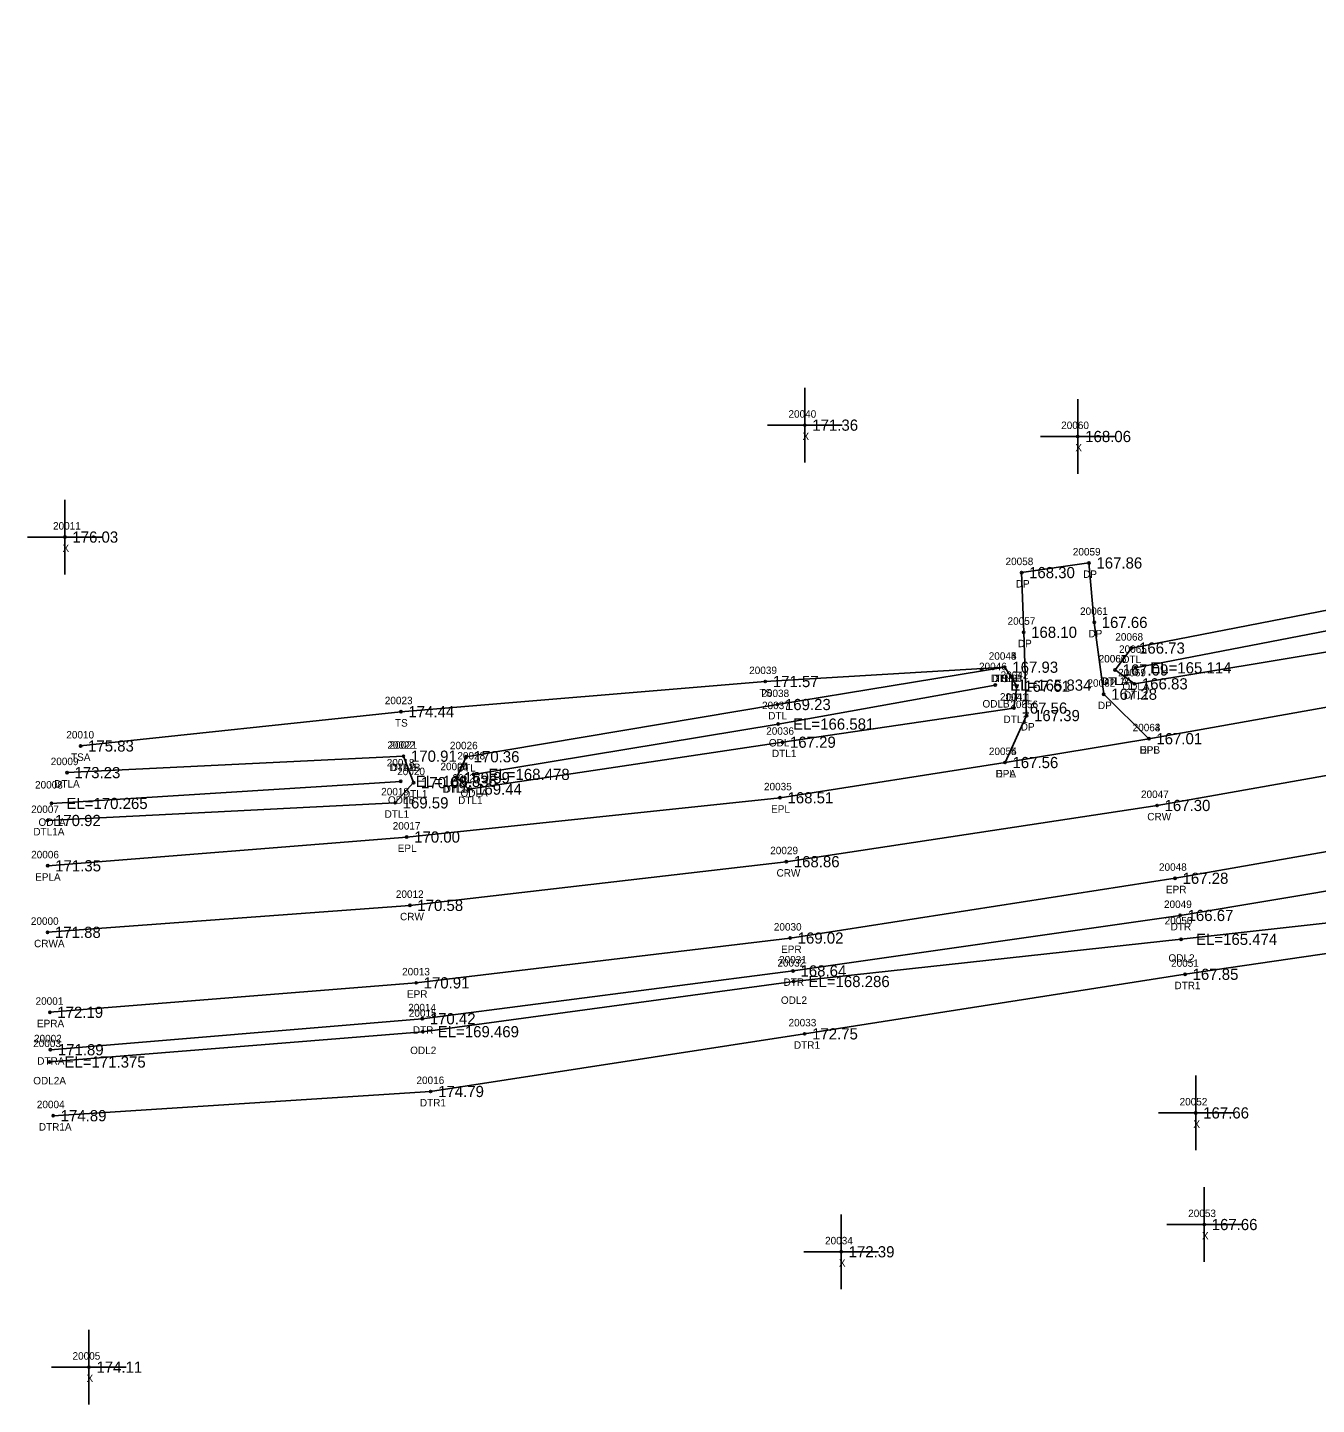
# Model space of a CAD drawing. Extents: x 2381545 to 2382928, y 1029933 to 1030589.
# Drawn here: x 2381544.5 to 2381717.1, y 1030195.9 to 1030380.3 of the extents above; entities that cross this region are included whole.
import ezdxf

# ---------------------------------------------------------------- set-up
doc = ezdxf.new("R2010")
doc.units = 0
for name, color, linetype in [('RD_DTM_BkLn1', 7, 'Continuous'), ('RD_DTM_BkLn2', 7, 'Continuous'), ('RD_DTM_BkLn_txCode', 7, 'Continuous'), ('RD_EX_Driveway', 7, 'Continuous'), ('RD_EX_Driveway_txCode', 7, 'Continuous'), ('RD_EX_H2O', 7, 'Continuous'), ('RD_EX_H2O_txCode', 7, 'Continuous'), ('RD_EX_Misc', 7, 'Continuous'), ('RD_EX_Misc_txCode', 7, 'Continuous'), ('RD_EX_Road', 7, 'Continuous'), ('RD_EX_Road_txCode', 7, 'Continuous'), ('RD_EX_TX_Driveway_ELEV', 7, 'Continuous'), ('RD_EX_TX_H2O_ELEV', 7, 'Continuous'), ('RD_EX_TX_Misc_ELEV', 7, 'Continuous'), ('RD_EX_TX_Road_ELEV', 7, 'Continuous'), ('RD_HC_Survey_ELEV', 7, 'Continuous'), ('RD_HC_Survey_txCode', 7, 'Continuous'), ('RD_SMD_Locator', 7, 'Continuous')]:
    doc.layers.add(name, color=color, linetype=linetype)

msp = doc.modelspace()

# ---------------------------------------------------------------- linework, layer by layer
at = {"layer": 'RD_DTM_BkLn1'}
msp.add_lwpolyline([(2381547.18, 1030259.1), (2381595.71, 1030262.71), (2381646.12, 1030268.56), (2381695.78, 1030276.09), (2381799.52, 1030294.49), (2381897.44, 1030312.39), (2382008.24, 1030333.66), (2382118.08, 1030354.86), (2382202.13, 1030371.04)], dxfattribs=at)
at = {"layer": 'RD_DTM_BkLn2'}
msp.add_lwpolyline([(2381551.61, 1030284.06), (2381594.51, 1030288.65), (2381643.31, 1030292.69), (2381675.39, 1030294.61)], dxfattribs=at)
at = {"layer": 'RD_EX_Driveway'}
msp.add_lwpolyline([(2381675.41, 1030281.84), (2381678.3, 1030288.13), (2381677.91, 1030299.29), (2381677.63, 1030307.28), (2381686.65, 1030308.57), (2381687.36, 1030300.61), (2381688.63, 1030290.99), (2381694.68, 1030285.03)], dxfattribs=at)
at = {"layer": 'RD_EX_H2O'}
for p, q in [((2381692.86, 1030294.53), (2381793.09, 1030313.94)), ((2381549.8, 1030280.49), (2381594.85, 1030282.69)), ((2381547.71, 1030276.36), (2381594.48, 1030279.32))]:
    msp.add_line(p, q, dxfattribs=at)
for points in [[(2381690.14, 1030294.24), (2381692.74, 1030292.38), (2381796.89, 1030309.66), (2381793.09, 1030313.94), (2381792.54, 1030316.64)], [(2381690.14, 1030294.24), (2381692.36, 1030297.17), (2381792.54, 1030316.64)], [(2381601.96, 1030279.81), (2381603.58, 1030278.28), (2381645.61, 1030284.56), (2381676.61, 1030289.13), (2381676.98, 1030292.06), (2381675.39, 1030294.61)], [(2381601.96, 1030279.81), (2381603.25, 1030282.62), (2381644.94, 1030289.61), (2381675.39, 1030294.61)], [(2381604.23, 1030280.25), (2381645.03, 1030286.99), (2381674.11, 1030292.21)], [(2381547.18, 1030274.08), (2381593.74, 1030276.44), (2381596.2, 1030279.15), (2381594.85, 1030282.69)], [(2381547.56, 1030243.37), (2381597.37, 1030247.52), (2381647.02, 1030253.93), (2381698.86, 1030261.36), (2381785.89, 1030275.89), (2381786.8, 1030272.08), (2381786.92, 1030266.26)], [(2381547.45, 1030241.73), (2381597.44, 1030245.79), (2381647.09, 1030252.51), (2381698.99, 1030258.16), (2381773.74, 1030266.5), (2381786.8, 1030272.08)], [(2381547.94, 1030234.54), (2381598.49, 1030237.78), (2381648.57, 1030245.5), (2381699.53, 1030253.48), (2381786.92, 1030266.26)]]:
    msp.add_lwpolyline(points, dxfattribs=at)
at = {"layer": 'RD_EX_Misc'}
for p, q in [((2381648.6, 1030322.03), (2381648.6, 1030332.03)), ((2381685.15, 1030320.51), (2381685.15, 1030330.51)), ((2381643.6, 1030327.03), (2381653.6, 1030327.03)), ((2381680.15, 1030325.51), (2381690.15, 1030325.51)), ((2381549.51, 1030307.04), (2381549.51, 1030317.04)), ((2381544.51, 1030312.04), (2381554.51, 1030312.04)), ((2381700.95, 1030229.91), (2381700.95, 1030239.91)), ((2381695.95, 1030234.91), (2381705.95, 1030234.91)), ((2381702.09, 1030214.96), (2381702.09, 1030224.96)), ((2381653.47, 1030211.31), (2381653.47, 1030221.31)), ((2381697.09, 1030219.96), (2381707.09, 1030219.96)), ((2381648.47, 1030216.31), (2381658.47, 1030216.31)), ((2381552.73, 1030195.86), (2381552.73, 1030205.86)), ((2381547.73, 1030200.86), (2381557.73, 1030200.86))]:
    msp.add_line(p, q, dxfattribs=at)
at = {"layer": 'RD_EX_Road'}
for points in [[(2381547.21, 1030268.01), (2381595.28, 1030271.86), (2381645.28, 1030277.12), (2381675.41, 1030281.84), (2381694.68, 1030285.03), (2381797.68, 1030303.35), (2381895.95, 1030322.08), (2382005.53, 1030342.57), (2382116.42, 1030363.72), (2382200, 1030380.28), (2382202.13, 1030371.04)], [(2381547.49, 1030248.39), (2381596.55, 1030252.33), (2381646.64, 1030258.33), (2381698.19, 1030266.34), (2381800.73, 1030284.35), (2381899.22, 1030302.47), (2382010.02, 1030323.79), (2382119.81, 1030345.41), (2382204.69, 1030361.31), (2382202.13, 1030371.04)]]:
    msp.add_lwpolyline(points, dxfattribs=at)
at = {"layer": 'RD_SMD_Locator'}
for centre in [(2381648.6, 1030327.03), (2381685.15, 1030325.51), (2381549.51, 1030312.04), (2381686.65, 1030308.57), (2381677.63, 1030307.28), (2381687.36, 1030300.61), (2381677.91, 1030299.29), (2381692.36, 1030297.17), (2381675.39, 1030294.61), (2381675.39, 1030294.61), (2381675.39, 1030294.61), (2381690.14, 1030294.24), (2381690.14, 1030294.24), (2381692.86, 1030294.53), (2381643.31, 1030292.69), (2381674.11, 1030292.21), (2381676.98, 1030292.06), (2381692.74, 1030292.38), (2381688.63, 1030290.99), (2381594.51, 1030288.65), (2381644.94, 1030289.61), (2381676.61, 1030289.13), (2381645.03, 1030286.99), (2381678.3, 1030288.13), (2381694.68, 1030285.03), (2381694.68, 1030285.03), (2381551.61, 1030284.06), (2381645.61, 1030284.56), (2381594.85, 1030282.69), (2381594.85, 1030282.69), (2381603.25, 1030282.62), (2381675.41, 1030281.84), (2381675.41, 1030281.84), (2381549.8, 1030280.49), (2381594.48, 1030279.32), (2381596.2, 1030279.15), (2381601.96, 1030279.81), (2381601.96, 1030279.81), (2381604.23, 1030280.25), (2381603.58, 1030278.28), (2381547.71, 1030276.36), (2381593.74, 1030276.44), (2381645.28, 1030277.12), (2381695.78, 1030276.09), (2381547.18, 1030274.08), (2381595.28, 1030271.86), (2381547.21, 1030268.01), (2381646.12, 1030268.56), (2381698.19, 1030266.34), (2381595.71, 1030262.71), (2381698.86, 1030261.36), (2381547.18, 1030259.1), (2381646.64, 1030258.33), (2381698.99, 1030258.16), (2381647.02, 1030253.93), (2381699.53, 1030253.48), (2381596.55, 1030252.33), (2381647.09, 1030252.51), (2381547.49, 1030248.39), (2381597.37, 1030247.52), (2381597.44, 1030245.79), (2381648.57, 1030245.5), (2381547.56, 1030243.37), (2381547.45, 1030241.73), (2381598.49, 1030237.78), (2381700.95, 1030234.91), (2381547.94, 1030234.54), (2381702.09, 1030219.96), (2381653.47, 1030216.31), (2381552.73, 1030200.86)]:
    msp.add_circle(centre, 0.15, dxfattribs=at)

# ---------------------------------------------------------------- texts
at = {"layer": 'RD_DTM_BkLn_txCode'}
for s, p in [('20045', (2381673.23, 1030295.61)), ('20039', (2381641.15, 1030293.69)), ('TSB', (2381674.12, 1030292.61)), ('20023', (2381592.35, 1030289.65)), ('TS', (2381642.51, 1030290.69)), ('TS', (2381593.71, 1030286.65)), ('20010', (2381549.7, 1030285.06)), ('TSA', (2381550.33, 1030282.06))]:
    msp.add_text(s, height=1, dxfattribs=at).set_placement(p)
at = {"layer": 'RD_EX_Driveway_txCode'}
for s, p in [('20059', (2381684.49, 1030309.57)), ('20058', (2381675.48, 1030308.28)), ('DP', (2381685.87, 1030306.57)), ('DP', (2381676.85, 1030305.28)), ('20061', (2381685.46, 1030301.61)), ('20057', (2381675.75, 1030300.29)), ('DP', (2381686.58, 1030298.61)), ('DP', (2381677.13, 1030297.29)), ('20062', (2381686.45, 1030291.99)), ('20056', (2381676.12, 1030289.13)), ('DP', (2381687.85, 1030288.99)), ('DP', (2381677.52, 1030286.13)), ('20063', (2381692.5, 1030286.03)), ('20055', (2381673.25, 1030282.84)), ('DPB', (2381693.43, 1030283.03)), ('DPA', (2381674.14, 1030279.84))]:
    msp.add_text(s, height=1, dxfattribs=at).set_placement(p)
at = {"layer": 'RD_EX_H2O_txCode'}
for s, p in [('20068', (2381690.18, 1030298.17)), ('20043', (2381673.23, 1030295.61)), ('20044', (2381673.23, 1030295.61)), ('20066', (2381687.94, 1030295.24)), ('20067', (2381687.96, 1030295.24)), ('20065', (2381690.68, 1030296.53)), ('DTL', (2381691.12, 1030295.17)), ('20046', (2381671.93, 1030294.21)), ('20042', (2381674.82, 1030293.06)), ('20069', (2381690.56, 1030293.38)), ('DTL1B', (2381673.51, 1030292.61)), ('DTLB', (2381673.67, 1030292.61)), ('DTL1A', (2381688.25, 1030292.24)), ('DTLA', (2381688.41, 1030292.24)), ('ODLA', (2381691.13, 1030291.53)), ('20038', (2381642.78, 1030290.61)), ('20041', (2381674.73, 1030290.13)), ('DTL1', (2381675.57, 1030290.06)), ('DTL1', (2381691.34, 1030290.38)), ('20037', (2381642.87, 1030288.99)), ('DTL', (2381643.7, 1030287.61)), ('ODLB', (2381672.39, 1030289.21)), ('DTL1', (2381675.2, 1030287.13)), ('20036', (2381643.43, 1030285.56)), ('ODL', (2381643.79, 1030283.99)), ('20022', (2381592.69, 1030283.69)), ('20021', (2381592.98, 1030283.69)), ('20026', (2381601.07, 1030283.62)), ('20028', (2381602.07, 1030282.25)), ('DTL1', (2381644.2, 1030282.56)), ('20009', (2381547.61, 1030281.49)), ('20018', (2381592.61, 1030281.32)), ('DTL1B', (2381592.97, 1030280.69)), ('DTLB', (2381593.14, 1030280.69)), ('20020', (2381594.01, 1030280.15)), ('20024', (2381599.8, 1030280.81)), ('20025', (2381599.8, 1030280.81)), ('DTL', (2381602, 1030280.62)), ('20008', (2381545.51, 1030278.36)), ('DTLA', (2381548.07, 1030278.49)), ('20027', (2381601.42, 1030279.28)), ('20019', (2381591.87, 1030277.44)), ('DTL1', (2381594.79, 1030277.15)), ('DTL1A', (2381600.06, 1030277.81)), ('DTLA', (2381600.23, 1030277.81)), ('ODLA', (2381602.49, 1030277.25)), ('20007', (2381544.99, 1030275.08)), ('ODLB', (2381592.77, 1030276.32)), ('DTL1', (2381602.17, 1030276.28)), ('ODLA', (2381545.97, 1030273.36)), ('DTL1', (2381592.33, 1030274.44)), ('DTL1A', (2381545.29, 1030272.08)), ('20049', (2381696.7, 1030262.36)), ('20050', (2381696.79, 1030260.16)), ('DTR', (2381697.59, 1030259.36)), ('20032', (2381644.93, 1030254.51)), ('20031', (2381645.15, 1030254.93)), ('ODL2', (2381697.3, 1030255.16)), ('20051', (2381697.65, 1030254.48)), ('DTR', (2381645.75, 1030251.93)), ('DTR1', (2381698.1, 1030251.48)), ('ODL2', (2381645.4, 1030249.51)), ('20014', (2381595.49, 1030248.52)), ('20015', (2381595.57, 1030247.79)), ('DTR', (2381596.1, 1030245.52)), ('20033', (2381646.42, 1030246.5)), ('20003', (2381545.26, 1030243.73)), ('20002', (2381545.37, 1030244.37)), ('DTR1', (2381647.14, 1030243.5)), ('DTRA', (2381545.81, 1030241.37)), ('ODL2', (2381595.75, 1030242.79)), ('ODL2A', (2381545.27, 1030238.73)), ('20016', (2381596.59, 1030238.78)), ('20004', (2381545.75, 1030235.54)), ('DTR1', (2381597.05, 1030235.78)), ('DTR1A', (2381546.02, 1030232.54))]:
    msp.add_text(s, height=1, dxfattribs=at).set_placement(p)
at = {"layer": 'RD_EX_Misc_txCode'}
for s, p in [('20040', (2381646.41, 1030328.03)), ('20060', (2381682.93, 1030326.51)), ('X', (2381648.29, 1030325.03)), ('X', (2381684.83, 1030323.51)), ('20011', (2381547.92, 1030313.04)), ('X', (2381549.19, 1030310.04)), ('20052', (2381698.79, 1030235.91)), ('X', (2381700.63, 1030232.91)), ('20053', (2381699.94, 1030220.96)), ('X', (2381701.78, 1030217.96)), ('20034', (2381651.31, 1030217.31)), ('X', (2381653.16, 1030214.31)), ('20005', (2381550.53, 1030201.86)), ('X', (2381552.41, 1030198.86))]:
    msp.add_text(s, height=1, dxfattribs=at).set_placement(p)
at = {"layer": 'RD_EX_Road_txCode'}
for s, p in [('20064', (2381692.5, 1030286.03)), ('20054', (2381673.25, 1030282.84)), ('EPL', (2381693.48, 1030283.03)), ('EPL', (2381674.21, 1030279.84)), ('20035', (2381643.13, 1030278.12)), ('EPL', (2381644.08, 1030275.12)), ('20017', (2381593.41, 1030272.86)), ('20006', (2381544.99, 1030269.01)), ('EPL', (2381594.08, 1030269.86)), ('20048', (2381696.03, 1030267.34)), ('EPLA', (2381545.52, 1030266.01)), ('EPR', (2381696.96, 1030264.34)), ('20030', (2381644.45, 1030259.33)), ('EPR', (2381645.42, 1030256.33)), ('20013', (2381594.67, 1030253.33)), ('20001', (2381545.58, 1030249.39)), ('EPR', (2381595.32, 1030250.33)), ('EPRA', (2381545.77, 1030246.39))]:
    msp.add_text(s, height=1, dxfattribs=at).set_placement(p)
at = {"layer": 'RD_EX_TX_Driveway_ELEV'}
for s, p in [('167.86', (2381687.65, 1030307.82)), ('168.30', (2381678.63, 1030306.53)), ('167.66', (2381688.36, 1030299.86)), ('168.10', (2381678.91, 1030298.54)), ('167.28', (2381689.63, 1030290.24)), ('167.39', (2381679.3, 1030287.38)), ('167.01', (2381695.68, 1030284.28)), ('167.56', (2381676.41, 1030281.09))]:
    msp.add_text(s, height=1.5, dxfattribs=at).set_placement(p)
at = {"layer": 'RD_EX_TX_H2O_ELEV'}
for s, p in [('166.73', (2381693.36, 1030296.42)), ('167.93', (2381676.39, 1030293.86)), ('167.93', (2381676.39, 1030293.86)), ('167.09', (2381691.14, 1030293.49)), ('167.09', (2381691.14, 1030293.49)), ('EL=165.114', (2381694.86, 1030293.78)), ('EL=165.834', (2381676.11, 1030291.46)), ('167.61', (2381677.98, 1030291.31)), ('166.83', (2381693.74, 1030291.63)), ('169.23', (2381645.94, 1030288.86)), ('167.56', (2381677.61, 1030288.38)), ('EL=166.581', (2381647.03, 1030286.24)), ('167.29', (2381646.61, 1030283.81)), ('170.91', (2381595.85, 1030281.94)), ('170.91', (2381595.85, 1030281.94)), ('170.36', (2381604.25, 1030281.87)), ('173.23', (2381550.8, 1030279.74)), ('EL=168.836', (2381596.48, 1030278.57)), ('170.08', (2381597.2, 1030278.4)), ('169.89', (2381602.96, 1030279.06)), ('169.89', (2381602.96, 1030279.06)), ('EL=168.478', (2381606.23, 1030279.5)), ('169.44', (2381604.58, 1030277.53)), ('EL=170.265', (2381549.71, 1030275.61)), ('169.59', (2381594.74, 1030275.69)), ('170.92', (2381548.18, 1030273.33)), ('166.67', (2381699.86, 1030260.61)), ('EL=165.474', (2381700.99, 1030257.41)), ('168.64', (2381648.02, 1030253.18)), ('167.85', (2381700.53, 1030252.73)), ('EL=168.286', (2381649.09, 1030251.76)), ('170.42', (2381598.37, 1030246.77)), ('EL=169.469', (2381599.44, 1030245.04)), ('172.75', (2381649.57, 1030244.75)), ('171.89', (2381548.56, 1030242.62)), ('EL=171.375', (2381549.45, 1030240.98)), ('174.79', (2381599.49, 1030237.03)), ('174.89', (2381548.94, 1030233.79))]:
    msp.add_text(s, height=1.5, dxfattribs=at).set_placement(p)
at = {"layer": 'RD_EX_TX_Misc_ELEV'}
for s, p in [('171.36', (2381649.6, 1030326.28)), ('168.06', (2381686.15, 1030324.76)), ('176.03', (2381550.51, 1030311.29)), ('167.93', (2381676.39, 1030293.86)), ('171.57', (2381644.31, 1030291.94)), ('174.44', (2381595.51, 1030287.9)), ('175.83', (2381552.61, 1030283.31)), ('167.66', (2381701.95, 1030234.16)), ('167.66', (2381703.09, 1030219.21)), ('172.39', (2381654.47, 1030215.56)), ('174.11', (2381553.73, 1030200.11))]:
    msp.add_text(s, height=1.5, dxfattribs=at).set_placement(p)
at = {"layer": 'RD_EX_TX_Road_ELEV'}
for s, p in [('167.01', (2381695.68, 1030284.28)), ('167.56', (2381676.41, 1030281.09)), ('168.51', (2381646.28, 1030276.37)), ('170.00', (2381596.28, 1030271.11)), ('171.35', (2381548.21, 1030267.26)), ('167.28', (2381699.19, 1030265.59)), ('169.02', (2381647.64, 1030257.58)), ('170.91', (2381597.55, 1030251.58)), ('172.19', (2381548.49, 1030247.64))]:
    msp.add_text(s, height=1.5, dxfattribs=at).set_placement(p)
at = {"layer": 'RD_HC_Survey_ELEV'}
for s, p in [('167.30', (2381696.78, 1030275.34)), ('168.86', (2381647.12, 1030267.81)), ('170.58', (2381596.71, 1030261.96)), ('171.88', (2381548.18, 1030258.35))]:
    msp.add_text(s, height=1.5, dxfattribs=at).set_placement(p)
at = {"layer": 'RD_HC_Survey_txCode'}
for s, p in [('20047', (2381693.62, 1030277.09)), ('CRW', (2381694.46, 1030274.09)), ('20029', (2381643.97, 1030269.56)), ('CRW', (2381644.81, 1030266.56)), ('20012', (2381593.83, 1030263.71)), ('20000', (2381544.95, 1030260.1)), ('CRW', (2381594.39, 1030260.71)), ('CRWA', (2381545.38, 1030257.1))]:
    msp.add_text(s, height=1, dxfattribs=at).set_placement(p)

doc.saveas('drawing.dxf')
